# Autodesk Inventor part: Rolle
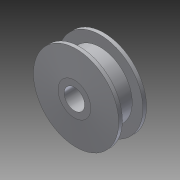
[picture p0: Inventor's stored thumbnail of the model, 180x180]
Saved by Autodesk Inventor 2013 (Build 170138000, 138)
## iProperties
Created: 2012-07
Part Number: Rolle
Material: Aluminium 6061
Document SubType Name: Modeling
Designer: rYan
Density: 2.71 g/cm^3
Mass: 0.52329 g
Surface Area: 3.55597 cm^2
Volume: 0.193096 cm^3
Author: rYan
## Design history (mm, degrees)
sketch "Skizze1"
  geometry: L1 (0, -1.9)-(0, 1.9); L2 (0, 1.9)-(2, 1.9); L3 (2, 1.9)-(5.2, 1.7); L4 (5.2, 1.7)-(5.2, 1.25); L5 (5.2, 1.25)-(3.9, 1.25); L6 (3.9, 1.25)-(3.9, -1.25); L7 (3.9, -1.25)-(5.2, -1.25); L8 (5.2, -1.25)-(5.2, -1.7); L9 (5.2, -1.7)-(2, -1.9); L10 (2, -1.9)-(0, -1.9); L11 (-1.04, 0)-(6.24, 0) reference; L12 (0, 2.66)-(0, -2.66) reference; 1 further point
  constraints: 20 end point, 6 parallel, 1 collinear, 1 perpendicular, 1 vertical, 4 other
  dimensions: "d0" = 0.2 distance from line of L3.end L2; "d3" = 3.8 distance between parallel lines of L10 L2; "d4" = 2.5 distance between parallel lines of L7 L5; "d5" = 1.3 distance between parallel lines of L4 L6; "d6" = 10.4 diameter of L8 L1; "d7" = 4 diameter of L2.end L1
revolve "Umdrehung1" sketch "Skizze1" stored, may be unused: angle "d8" = 90 deg
sketch "Skizze2"
  geometry: 1 further point
hole "Bohrung1" sketch "Skizze2" at (0, 0) diameter "d9" = 2.5; stored, may be unused: countersink angle "d13" = 90 deg, drill point angle "d15" = 118 deg; dims "d10" = 6, "d11" = 4, "d12" = 2, "d14" = 8
node "Volumenkörper1"
